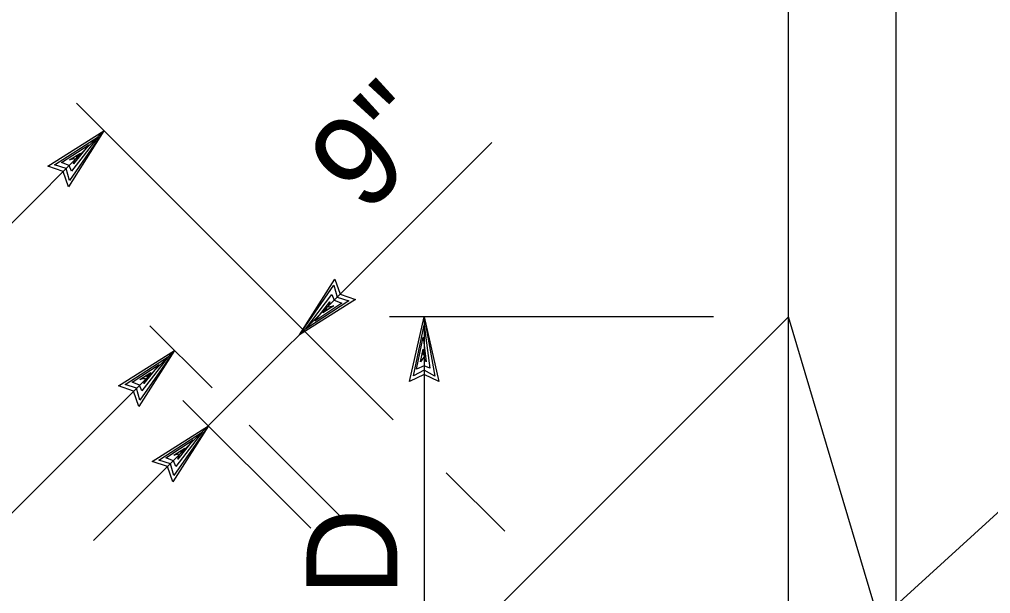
# Model space of a CAD drawing. Extents: x -0.08 to 2.83, y -0.03 to 1.92.
# Drawn here: x 0.4158 to 0.555, y 1.5488 to 1.6311 of the extents above; entities that cross this region are included whole.
import ezdxf

# ---------------------------------------------------------------- set-up
doc = ezdxf.new("R2010")
doc.units = 0
for name, color, linetype in [('50', 7, 'Continuous'), ('55', 7, 'Continuous'), ('57', 7, 'Continuous')]:
    doc.layers.add(name, color=color, linetype=linetype)

msp = doc.modelspace()

# ---------------------------------------------------------------- linework, layer by layer
at = {"layer": '50'}
for p, q in [((0.5260279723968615, 1.5119855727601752), (0.5260279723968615, 1.7092591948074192)), ((0.5414577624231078, 1.5112145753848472), (0.5414577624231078, 1.7092591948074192)), ((0.2614347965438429, 1.3238261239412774), (0.5260279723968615, 1.5884460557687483)), ((0.5472320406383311, 1.5170216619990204), (0.5260279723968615, 1.5884460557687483))]:
    msp.add_line(p, q, dxfattribs=at)
at = {"layer": '55'}
for p, q in [((0.46937241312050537, 1.5736640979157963), (0.4239838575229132, 1.6190526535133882)), ((0.19905946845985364, 1.3861981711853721), (0.42793742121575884, 1.6150990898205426)), ((0.41990592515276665, 1.6100170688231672), (0.42793742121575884, 1.6150990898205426)), ((0.4208508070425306, 1.610204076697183), (0.4270876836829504, 1.614236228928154)), ((0.42793742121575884, 1.6150990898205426), (0.42285211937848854, 1.6070741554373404)), ((0.42793742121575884, 1.6150990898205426), (0.4229931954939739, 1.6079731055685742)), ((0.4270876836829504, 1.614236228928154), (0.42328190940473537, 1.6092985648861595)), ((0.4218514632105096, 1.6105387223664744), (0.42575238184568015, 1.6131076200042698)), ((0.42575238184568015, 1.6131076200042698), (0.4235607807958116, 1.6103484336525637)), ((0.4835273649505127, 1.6134020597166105), (0.4264577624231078, 1.5563556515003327)), ((0.4229931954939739, 1.6109192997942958), (0.4245581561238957, 1.6119133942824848)), ((0.4245581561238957, 1.6119133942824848), (0.42394791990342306, 1.6112965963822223)), ((0.42209096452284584, 1.6092559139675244), (0.41990592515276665, 1.6100170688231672)), ((0.4225240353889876, 1.6096857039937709), (0.4208508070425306, 1.610204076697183)), ((0.42294070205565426, 1.6101056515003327), (0.4218514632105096, 1.6105387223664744)), ((0.42328190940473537, 1.6092985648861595), (0.42294070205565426, 1.6101056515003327)), ((0.4237970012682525, 1.6110603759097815), (0.4229931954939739, 1.6109192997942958)), ((0.4235607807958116, 1.6103484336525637), (0.4237970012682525, 1.6110603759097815)), ((0.42285211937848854, 1.6070741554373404), (0.42209096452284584, 1.6092559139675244)), ((0.4229931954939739, 1.6079731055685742), (0.4225240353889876, 1.6096857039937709)), ((0.4559393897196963, 1.5858274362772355), (0.46102469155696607, 1.5938458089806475)), ((0.46102469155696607, 1.5938458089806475), (0.4617891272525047, 1.5916673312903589)), ((0.4559393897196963, 1.5858274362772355), (0.4608836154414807, 1.592950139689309)), ((0.4608836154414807, 1.592950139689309), (0.4613593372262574, 1.5912408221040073)), ((0.4639741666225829, 1.5909061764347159), (0.4559393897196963, 1.5858274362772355)), ((0.4567956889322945, 1.5866804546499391), (0.4606014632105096, 1.5916213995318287)), ((0.4630194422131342, 1.5907158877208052), (0.4567956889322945, 1.5866804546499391)), ((0.4581277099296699, 1.5878156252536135), (0.4603127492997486, 1.5905780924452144)), ((0.46202206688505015, 1.5903812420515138), (0.4581277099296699, 1.5878156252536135)), ((0.4603127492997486, 1.5905780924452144), (0.4600765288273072, 1.5898661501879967)), ((0.4606014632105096, 1.5916213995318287), (0.46092954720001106, 1.5908143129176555)), ((0.46092954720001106, 1.5908143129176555), (0.46202206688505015, 1.5903812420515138)), ((0.4613593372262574, 1.5912408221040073), (0.4630194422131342, 1.5907158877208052)), ((0.4617891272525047, 1.5916673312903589), (0.4639741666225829, 1.5909061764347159)), ((0.4608836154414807, 1.5900072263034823), (0.4593153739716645, 1.5890065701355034)), ((0.4593153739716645, 1.5890065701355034), (0.459932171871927, 1.5896233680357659)), ((0.4600765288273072, 1.5898661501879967), (0.4608836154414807, 1.5900072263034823)), ((0.5152471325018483, 1.5884460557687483), (0.46886600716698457, 1.5884460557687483)), ((0.471728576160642, 1.5791776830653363), (0.47381190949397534, 1.5884460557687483)), ((0.47381190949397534, 1.5884460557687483), (0.47381190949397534, 1.5170216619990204)), ((0.47381190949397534, 1.5884460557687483), (0.4758985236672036, 1.5791776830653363)), ((0.47381190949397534, 1.5884460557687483), (0.4753604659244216, 1.579912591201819)), ((0.4434262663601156, 1.5782322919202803), (0.43451308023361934, 1.5871421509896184)), ((0.47226663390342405, 1.5799847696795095), (0.47381190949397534, 1.5872419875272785)), ((0.47381190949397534, 1.5872419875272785), (0.4746189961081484, 1.5810576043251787)), ((0.4727357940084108, 1.580923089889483), (0.4736773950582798, 1.5854932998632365)), ((0.4736773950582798, 1.5854932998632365), (0.47408093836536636, 1.5819992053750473)), ((0.22776353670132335, 1.3733241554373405), (0.4380358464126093, 1.5836161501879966)), ((0.4300076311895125, 1.5785341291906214), (0.4380358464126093, 1.5836161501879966)), ((0.4380358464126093, 1.5836161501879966), (0.43294726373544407, 1.5755813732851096)), ((0.4380358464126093, 1.5836161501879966), (0.4330949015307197, 1.576493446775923)), ((0.47327385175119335, 1.5819992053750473), (0.4736773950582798, 1.583816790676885)), ((0.4736773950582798, 1.583816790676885), (0.4736773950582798, 1.5829375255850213)), ((0.4309557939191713, 1.5787178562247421), (0.43717626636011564, 1.582763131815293)), ((0.43717626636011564, 1.582763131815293), (0.4333803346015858, 1.5778221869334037)), ((0.47374629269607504, 1.582671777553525), (0.47327385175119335, 1.5819992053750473)), ((0.47408093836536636, 1.5819992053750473), (0.47374629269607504, 1.582671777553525)), ((0.43195645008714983, 1.5790525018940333), (0.43584752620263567, 1.5816181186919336)), ((0.43584752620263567, 1.5816181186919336), (0.433662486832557, 1.5788654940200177)), ((0.47381190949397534, 1.5807885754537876), (0.47226663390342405, 1.5799847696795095)), ((0.47381190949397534, 1.5813922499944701), (0.4727357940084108, 1.580923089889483)), ((0.4746189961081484, 1.5810576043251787), (0.47381190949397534, 1.5813922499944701)), ((0.4753604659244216, 1.579912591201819), (0.47381190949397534, 1.5807885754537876)), ((0.4330949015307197, 1.5794363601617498), (0.43465986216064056, 1.5804370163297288)), ((0.43390526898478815, 1.5795741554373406), (0.4330949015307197, 1.5794363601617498)), ((0.433662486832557, 1.5788654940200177), (0.43390526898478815, 1.5795741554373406)), ((0.43465986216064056, 1.5804370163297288), (0.4340430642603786, 1.5798169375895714)), ((0.47381190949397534, 1.5801849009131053), (0.471728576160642, 1.5791776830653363)), ((0.4758985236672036, 1.5791776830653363), (0.47381190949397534, 1.5801849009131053)), ((0.4321893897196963, 1.5777729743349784), (0.4300076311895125, 1.5785341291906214)), ((0.4326191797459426, 1.578196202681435), (0.4309557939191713, 1.5787178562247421)), ((0.43304896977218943, 1.5786292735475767), (0.43195645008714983, 1.5790525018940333)), ((0.4330949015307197, 1.576493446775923), (0.4326191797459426, 1.578196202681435)), ((0.4333803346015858, 1.5778221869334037), (0.43304896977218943, 1.5786292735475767)), ((0.43294726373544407, 1.5755813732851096), (0.4321893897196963, 1.5777729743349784)), ((0.4575609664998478, 1.558119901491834), (0.43923991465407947, 1.576440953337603)), ((0.43486655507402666, 1.5677073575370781), (0.44289477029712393, 1.5727860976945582)), ((0.44289477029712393, 1.5727860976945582), (0.43780946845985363, 1.5647578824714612)), ((0.44289477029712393, 1.5727860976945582), (0.4379571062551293, 1.565663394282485)), ((0.4618839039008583, 1.5597763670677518), (0.44876091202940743, 1.5728943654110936)), ((0.4358147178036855, 1.5678976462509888), (0.44204175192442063, 1.5719297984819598)), ((0.44204175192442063, 1.5719297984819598), (0.4382392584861, 1.566992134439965)), ((0.4368186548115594, 1.568229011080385), (0.4407162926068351, 1.5707880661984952)), ((0.4379571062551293, 1.5686030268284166), (0.43952206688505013, 1.5696069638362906)), ((0.4407162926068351, 1.5707880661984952), (0.43852469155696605, 1.5680354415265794)), ((0.43952206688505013, 1.5696069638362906), (0.43890198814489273, 1.5689901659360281)), ((0.4379046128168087, 1.5677992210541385), (0.4368186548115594, 1.568229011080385)), ((0.43876419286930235, 1.5687473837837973), (0.4379571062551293, 1.5686030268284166)), ((0.43852469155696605, 1.5680354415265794), (0.43876419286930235, 1.5687473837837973)), ((0.43705159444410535, 1.56694948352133), (0.43486655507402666, 1.5677073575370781)), ((0.43747810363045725, 1.5673694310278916), (0.4358147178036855, 1.5678976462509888)), ((0.43780946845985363, 1.5647578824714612), (0.43705159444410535, 1.56694948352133)), ((0.4379571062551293, 1.565663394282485), (0.43747810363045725, 1.5673694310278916)), ((0.4382392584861, 1.566992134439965), (0.4379046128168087, 1.5677992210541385)), ((0.4853586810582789, 1.5576876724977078), (0.4769735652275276, 1.5660678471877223)), ((0.531680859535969, 1.5382683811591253), (0.5569794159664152, 1.561217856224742))]:
    msp.add_line(p, q, dxfattribs=at)

# ---------------------------------------------------------------- texts
at = {"layer": '57'}
for s, rotation, p in [('9"', 45.003347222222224, (0.46540289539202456, 1.6028764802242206)), ('D', 90, (0.4699677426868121, 1.5483915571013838))]:
    msp.add_text(s, height=0.013020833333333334, rotation=rotation, dxfattribs=at).set_placement(p)

doc.saveas('drawing.dxf')
